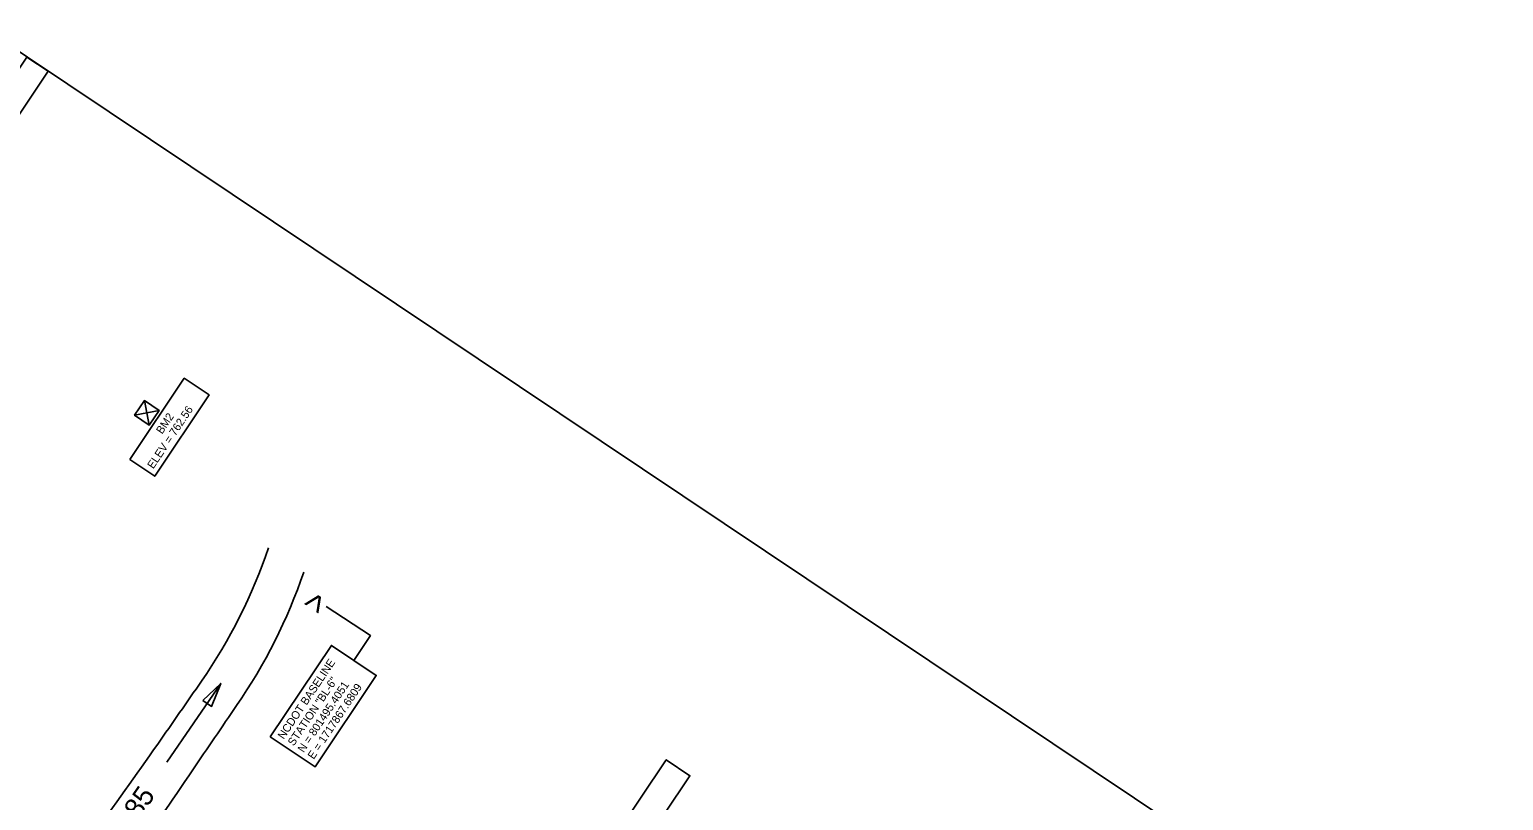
# Model space of a CAD drawing. Extents: x 1716977 to 1718461, y 800056 to 801805.
# Drawn here: x 1717724 to 1718461, y 801395 to 801781 of the extents above; entities that cross this region are included whole.
import ezdxf

# ---------------------------------------------------------------- set-up
doc = ezdxf.new("R2010")
doc.units = 0
for name, color, linetype in [('CTL Sheet Border CELL', 7, 'Continuous'), ('CTL Sheet Text', 7, 'Continuous'), ('Default', 7, 'Continuous'), ('Exist Roads EOP', 7, 'Continuous'), ('Old_Level_57', 7, 'Continuous'), ('Proposed Right of Way Monument PSD Text', 7, 'Continuous'), ('Sheet Data Field CELL', 7, 'Continuous')]:
    doc.layers.add(name, color=color, linetype=linetype)

msp = doc.modelspace()

# ---------------------------------------------------------------- linework, layer by layer
at = {"layer": 'CTL Sheet Border CELL'}
for points in [[(1717702.35, 801780.65), (1716976.84, 800696.7), (1717735.6, 800188.84), (1718461.11, 801272.8)], [(1717964.52, 801299.01), (1718042.51, 801415.52), (1718054.41, 801407.56), (1717976.43, 801291.06)]]:
    msp.add_lwpolyline(points, close=True, dxfattribs=at)
at = {"layer": 'CTL Sheet Text'}
msp.add_line((1717792.9, 801414.27), (1717819.87, 801453.66), dxfattribs=at)
msp.add_lwpolyline([(1717810.85, 801445.22), (1717815.26, 801442.2), (1717819.87, 801453.66)], close=True, dxfattribs=at)
at = {"layer": 'Default'}
for points in [[(1717774.39, 801565.62), (1717801.59, 801606.26), (1717814.05, 801597.92), (1717786.85, 801557.28)], [(1717844.55, 801426.99), (1717875.15, 801472.71), (1717897.58, 801457.69), (1717866.98, 801411.97)]]:
    msp.add_lwpolyline(points, close=True, dxfattribs=at)
msp.add_lwpolyline([(1717886.37, 801465.2), (1717894.67, 801477.62), (1717872.5, 801492.23)], dxfattribs=at)
at = {"layer": 'Exist Roads EOP'}
for centre in [(1717586.15, 801609.36), (1717603.68, 801597.16)]:
    msp.add_arc(centre, 272.19, 325.40539, 341.17229, dxfattribs=at)
for points in [[(1717704.66, 801304.87), (1717720.57, 801327.61), (1717755.53, 801377.08), (1717788.31, 801423.35), (1717810.22, 801454.82)], [(1717723, 801292.11), (1717738.53, 801314.79), (1717747.21, 801327.08), (1717756.08, 801339.25), (1717764.97, 801351.4), (1717773.68, 801363.68), (1717805.81, 801410.44), (1717827.75, 801442.62)]]:
    msp.add_spline(points, degree=3, dxfattribs=at)
at = {"layer": 'Old_Level_57'}
for p, q in [((1717781.65, 801595.12), (1717784.08, 801582.85)), ((1717776.73, 801587.77), (1717789, 801590.2))]:
    msp.add_line(p, q, dxfattribs=at)
msp.add_lwpolyline([(1717784.08, 801582.85), (1717789, 801590.2), (1717781.65, 801595.12), (1717776.73, 801587.77)], close=True, dxfattribs=at)
for points in [[(1717782.86, 801588.99), (1717781.65, 801595.12), (1717776.73, 801587.77), (1717782.86, 801588.99)], [(1717782.86, 801588.99), (1717784.08, 801582.85), (1717789, 801590.2), (1717782.86, 801588.99)]]:
    msp.add_lwpolyline(points, dxfattribs=at)
at = {"layer": 'Sheet Data Field CELL'}
msp.add_lwpolyline([(1717626.73, 801623.12), (1717722.94, 801766.87), (1717733.58, 801759.75), (1717637.37, 801616)], close=True, dxfattribs=at)

# ---------------------------------------------------------------- texts
at = {"layer": 'CTL Sheet Text'}
msp.add_text('TO BUS I-85', height=10, rotation=55.59655, dxfattribs=at).set_placement((1717744.13, 801334.6))
at = {"layer": 'Old_Level_57'}
msp.add_text('>', height=11.74, rotation=56.21926, dxfattribs=at).set_placement((1717869.3, 801487.26))
at = {"layer": 'Proposed Right of Way Monument PSD Text'}
for s, p in [('ELEV = 762.56', (1717786.11, 801560.67)), ('BM2', (1717790.52, 801578.04)), ('NCDOT BASELINE', (1717851.34, 801425.45)), ('STATION "BL-6"', (1717856.32, 801422.12)), ('N = 801495.4051', (1717861.31, 801418.78)), ('E = 1717867.6809', (1717866.3, 801415.44))]:
    msp.add_text(s, height=4, rotation=56.20506, dxfattribs=at).set_placement(p)

doc.saveas('drawing.dxf')
